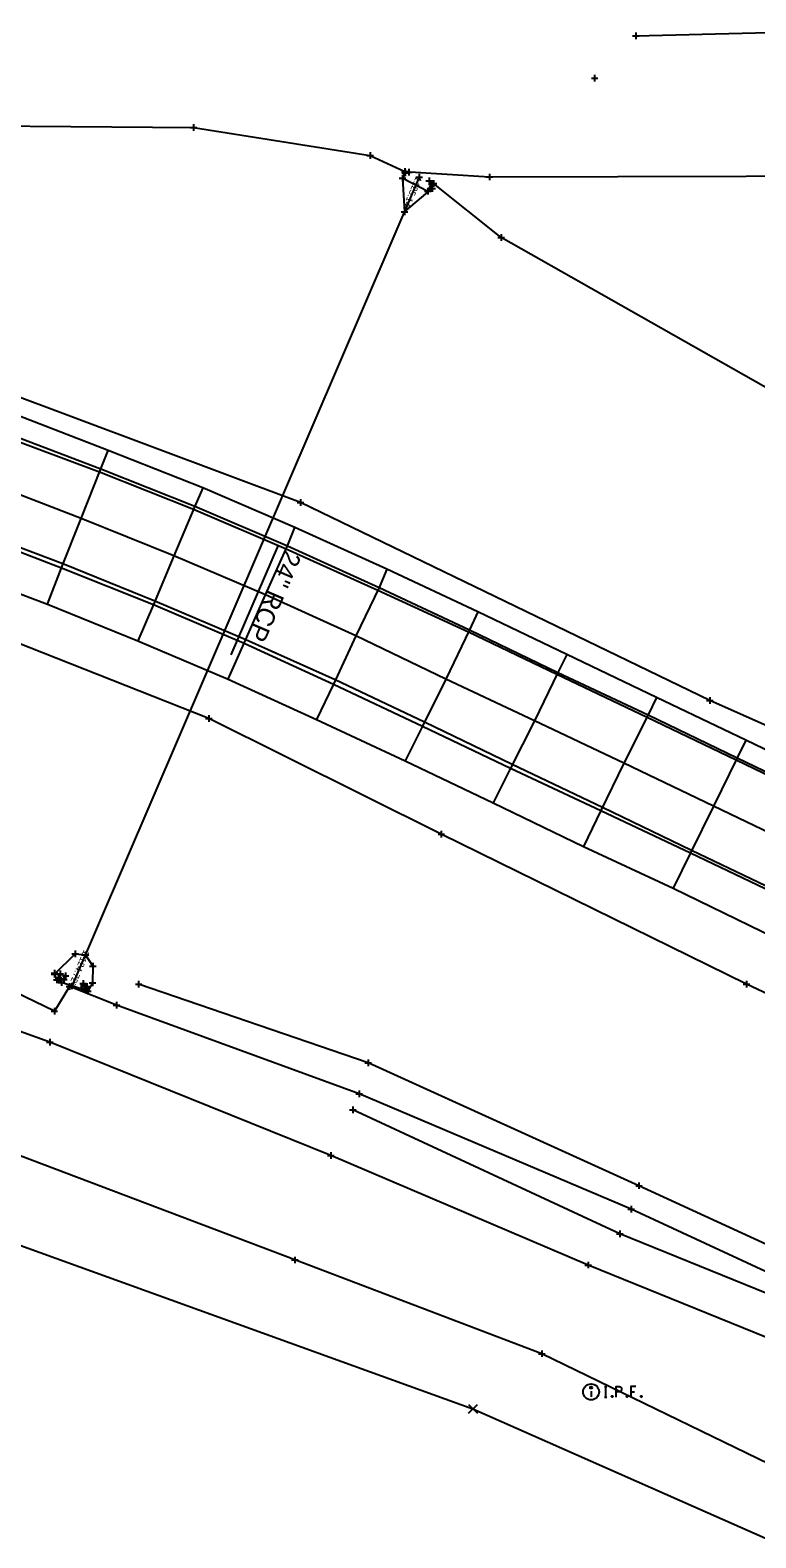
# Model space of a CAD drawing. Extents: x 207090 to 277928, y 600777 to 621109.
# Drawn here: x 259988 to 260097.7, y 611751.4 to 611979.1 of the extents above; entities that cross this region are included whole.
import ezdxf

# ---------------------------------------------------------------- set-up
doc = ezdxf.new("R2010")
doc.units = 0
for name, color, linetype in [('ATDIMS', 7, 'Continuous'), ('DR_X_Ditch', 7, 'Continuous'), ('DR_X_Headwall', 7, 'Continuous'), ('DR_X_Storm_Sewer', 7, 'Continuous'), ('DR_X_Text', 7, 'Continuous'), ('DT_X_Break_Line', 7, 'Continuous'), ('PM_P_Channelizing_Line', 7, 'Continuous'), ('PM_P_Edge_Line', 7, 'Continuous'), ('PM_P_Lane_Line', 7, 'Continuous'), ('PM_P_Stop_Line', 7, 'Continuous'), ('PM_X_Edge_Line', 7, 'Continuous'), ('PV_X_EOP', 7, 'Continuous'), ('PV_X_Joint', 7, 'Continuous'), ('PV_X_Shoulder_Aggregate', 7, 'Continuous'), ('SC_ProfileRun2', 7, 'Continuous'), ('SV_X_Break_Lines', 7, 'Continuous'), ('SV_X_Terrain_Boundary', 7, 'Continuous'), ('SV_X_Toe_of_Slope', 7, 'Continuous')]:
    doc.layers.add(name, color=color, linetype=linetype)

msp = doc.modelspace()

# ---------------------------------------------------------------- linework, layer by layer
at = {"layer": 'DR_X_Ditch'}
for points in [[(259994.32, 611834.74), (259993.95, 611834.65), (259991.68, 611830.94), (259953.06, 611849.58), (259908.97, 611863.06), (259861.24, 611870.04), (259813, 611875.04), (259773.78, 611878.41), (259728.19, 611880.81), (259679.51, 611881.44), (259609.96, 611884.9), (259573.89, 611884.86), (259525.74, 611886.2)], [(260922.71, 611564.11), (260890.1, 611570.61), (260838.53, 611574.76), (260802.48, 611577.5), (260766.37, 611577.17), (260721.33, 611574.97), (260650.56, 611573.72), (260623.07, 611583.7), (260580.3, 611596.7), (260534.96, 611609.27), (260480.65, 611625.85), (260438.14, 611643.07), (260395.35, 611661.63), (260359.84, 611676.62), (260316.28, 611695.06), (260281.01, 611710.64), (260238.37, 611728.41), (260199.78, 611745.66), (260157.66, 611763.38), (260118.67, 611782.58), (260078.85, 611801.04), (260037.76, 611818.47), (260001.09, 611831.86), (259993.95, 611834.65)]]:
    msp.add_lwpolyline(points, dxfattribs=at)
at = {"layer": 'DR_X_Headwall'}
for p, q in [((259992.33, 611835.96), (259992.58, 611836.57)), ((259995.73, 611834.41), (259996.02, 611835.14))]:
    msp.add_line(p, q, dxfattribs=at)
for points in [[(260044.7, 611957.54), (260044.32, 611956.73), (260048.11, 611954.79), (260048.7, 611955.83)], [(259992.58, 611836.57), (259993.39, 611836.26), (259993.11, 611835.72), (259992.33, 611835.96)], [(259995.73, 611834.41), (259996.36, 611834.16), (259996.61, 611834.68), (259996.02, 611835.14)]]:
    msp.add_lwpolyline(points, dxfattribs=at)
at = {"layer": 'DR_X_Storm_Sewer'}
msp.add_line((260046.81, 611956.88), (259994.32, 611834.74), dxfattribs=at)
at = {"layer": 'DR_X_Text'}
msp.add_line((260018.42, 611884.73), (260025.55, 611901.32), dxfattribs=at)
at = {"layer": 'DT_X_Break_Line'}
msp.add_lwpolyline([(259527, 611849.97), (259626.95, 611842.34), (259741, 611827.05), (259865.07, 611829.81), (259960.08, 611805.1), (260054.94, 611770.89), (260146.45, 611730.46), (260219.24, 611692.26), (260311.2, 611653.27), (260395, 611624.63), (260483.4, 611590.72), (260567.09, 611557.23), (260605.33, 611542.61), (260696.47, 611540.48), (260809.17, 611536.63), (260899.87, 611536.02), (260901.21, 611486.51)], dxfattribs=at)
at = {"layer": 'PM_P_Channelizing_Line'}
msp.add_line((260072.79, 611773.57), (260072.79, 611772.68), dxfattribs=at)
for points in [[(260074.82, 611774.25), (260075.17, 611774.25)], [(260075, 611772.65), (260075, 611774.25)], [(260076.56, 611772.65), (260076.56, 611774.25), (260077.09, 611774.25), (260077.15, 611774.24), (260077.22, 611774.21), (260077.26, 611774.19), (260077.29, 611774.16), (260077.33, 611774.1), (260077.37, 611774.04), (260077.39, 611773.94), (260077.39, 611773.78), (260077.38, 611773.73), (260077.36, 611773.66), (260077.31, 611773.57), (260077.27, 611773.53), (260077.24, 611773.51), (260077.18, 611773.48), (260077.09, 611773.47), (260076.56, 611773.47)], [(260079.57, 611774.25), (260078.81, 611774.25), (260078.81, 611772.65)], [(260078.81, 611773.47), (260079.35, 611773.47)], [(260074.82, 611772.65), (260075.17, 611772.65)], [(260075.96, 611772.86), (260076.01, 611772.86), (260076.04, 611772.84), (260076.08, 611772.79), (260076.08, 611772.73), (260076.04, 611772.68), (260076.01, 611772.65), (260075.96, 611772.65), (260075.92, 611772.68), (260075.89, 611772.73), (260075.89, 611772.79), (260075.92, 611772.84), (260075.96, 611772.86)], [(260078.21, 611772.86), (260078.26, 611772.86), (260078.29, 611772.84), (260078.33, 611772.79), (260078.33, 611772.73), (260078.29, 611772.68), (260078.26, 611772.65), (260078.21, 611772.65), (260078.17, 611772.68), (260078.14, 611772.73), (260078.14, 611772.79), (260078.17, 611772.84), (260078.21, 611772.86)], [(260080.35, 611772.86), (260080.41, 611772.86), (260080.44, 611772.84), (260080.48, 611772.79), (260080.48, 611772.73), (260080.44, 611772.68), (260080.41, 611772.65), (260080.35, 611772.65), (260080.32, 611772.68), (260080.29, 611772.73), (260080.29, 611772.79), (260080.32, 611772.84), (260080.35, 611772.86)]]:
    msp.add_lwpolyline(points, dxfattribs=at)
for centre, radius in [((260072.79, 611773.45), 1.2), ((260072.79, 611774.1), 0.16)]:
    msp.add_circle(centre, radius, dxfattribs=at)
at = {"layer": 'PM_P_Edge_Line'}
for points in [[(260941.7, 611641.82), (260872.52, 611643.41), (260802.13, 611645.93), (260739.12, 611642.18), (260643.19, 611651.33), (260585.03, 611658.8), (260513.53, 611682.15), (260464, 611705.03), (260398.1, 611738.54), (260342.54, 611761.22), (260280.51, 611790.45), (260220.82, 611821.35), (260149.95, 611851.52), (260090.72, 611877.86), (260028.89, 611907.76), (259972.46, 611928.83), (259918.28, 611945.99), (259861.48, 611959.13), (259802.38, 611969.56)], [(260619.36, 611566.48), (260576.53, 611581.12), (260531.14, 611596.48), (260474.62, 611616.67), (260434.35, 611631.77), (260391.22, 611651.53), (260353.46, 611665.22), (260309.89, 611681.18), (260273.05, 611696.19), (260231.58, 611714.55), (260192.39, 611733.11), (260152.26, 611751.99), (260115.57, 611775.09), (260072.37, 611792.61), (260033.48, 611809.15), (259991.01, 611826.28), (259950.11, 611840.93)]]:
    msp.add_lwpolyline(points, dxfattribs=at)
at = {"layer": 'PM_P_Lane_Line'}
msp.add_lwpolyline([(260617.29, 611547.1), (260564.97, 611566.43), (260527.38, 611581.13), (260467.61, 611603.71), (260430.24, 611617.6), (260385.39, 611634.96), (260347.72, 611648.56), (260302.9, 611665.18), (260265.68, 611679.36), (260222.59, 611700.28), (260186.67, 611718.31), (260144.42, 611739.84), (260108.32, 611758.38), (260065.34, 611779.22), (260028.03, 611793.37), (259983.16, 611810.37)], dxfattribs=at)
at = {"layer": 'PM_P_Stop_Line'}
for p, q in [((260079.54, 611978.73), (260079.54, 611977.73)), ((260079.04, 611978.23), (260080.04, 611978.23)), ((260079.54, 611978.23), (260079.54, 611978.23)), ((260012.72, 611964.89), (260012.72, 611963.89)), ((260012.22, 611964.39), (260013.22, 611964.39)), ((260012.72, 611964.39), (260012.72, 611964.39)), ((260038.89, 611960.15), (260039.89, 611960.15)), ((260039.39, 611960.65), (260039.39, 611959.65)), ((260039.39, 611960.15), (260039.39, 611960.15)), ((260044.66, 611958.26), (260044.66, 611957.26)), ((260044.7, 611958.04), (260044.7, 611957.04)), ((260045.25, 611958.15), (260045.25, 611957.15)), ((260043.77, 611956.74), (260044.77, 611956.74)), ((260043.82, 611956.73), (260044.82, 611956.73)), ((260044.16, 611957.76), (260045.16, 611957.76)), ((260044.2, 611957.54), (260045.2, 611957.54)), ((260044.27, 611957.24), (260044.27, 611956.24)), ((260044.27, 611956.74), (260044.27, 611956.74)), ((260044.32, 611957.23), (260044.32, 611956.23)), ((260044.32, 611956.73), (260044.32, 611956.73)), ((260044.66, 611957.76), (260044.66, 611957.76)), ((260044.7, 611957.54), (260044.7, 611957.54)), ((260044.75, 611957.65), (260045.75, 611957.65)), ((260045.25, 611957.65), (260045.25, 611957.65)), ((260047.82, 611956.35), (260048.82, 611956.35)), ((260048.2, 611955.83), (260049.2, 611955.83)), ((260048.32, 611956.85), (260048.32, 611955.85)), ((260048.32, 611956.35), (260048.32, 611956.35)), ((260048.47, 611955.93), (260049.47, 611955.93)), ((260048.7, 611956.33), (260048.7, 611955.33)), ((260048.7, 611955.83), (260048.7, 611955.83)), ((260048.76, 611955.65), (260048.76, 611954.65)), ((260048.97, 611956.43), (260048.97, 611955.43)), ((260048.97, 611955.93), (260048.97, 611955.93)), ((260056.93, 611956.91), (260057.93, 611956.91)), ((260057.43, 611957.41), (260057.43, 611956.41)), ((260057.43, 611956.91), (260057.43, 611956.91)), ((260047.61, 611954.79), (260048.61, 611954.79)), ((260048.11, 611955.29), (260048.11, 611954.29)), ((260048.11, 611954.79), (260048.11, 611954.79)), ((260048.26, 611955.15), (260049.26, 611955.15)), ((260048.76, 611955.15), (260048.76, 611955.15)), ((260044.09, 611951.63), (260045.09, 611951.63)), ((260044.59, 611952.13), (260044.59, 611951.13)), ((260044.59, 611951.63), (260044.59, 611951.63)), ((260058.71, 611947.76), (260059.71, 611947.76)), ((260059.21, 611948.26), (260059.21, 611947.26)), ((260059.21, 611947.76), (260059.21, 611947.76)), ((260028.39, 611907.76), (260029.39, 611907.76)), ((260028.89, 611908.26), (260028.89, 611907.26)), ((260028.89, 611907.76), (260028.89, 611907.76)), ((260090.72, 611878.36), (260090.72, 611877.36)), ((260090.22, 611877.86), (260091.22, 611877.86)), ((260090.72, 611877.86), (260090.72, 611877.86)), ((260014.54, 611875.15), (260015.54, 611875.15)), ((260015.04, 611875.65), (260015.04, 611874.65)), ((260015.04, 611875.15), (260015.04, 611875.15)), ((260049.66, 611857.67), (260050.66, 611857.67)), ((260050.16, 611858.17), (260050.16, 611857.17)), ((260050.16, 611857.67), (260050.16, 611857.67)), ((259994.33, 611839.58), (259995.33, 611839.58)), ((259994.83, 611840.08), (259994.83, 611839.08)), ((259994.83, 611839.58), (259994.83, 611839.58)), ((259995.91, 611839.43), (259996.91, 611839.43)), ((259996.41, 611839.93), (259996.41, 611838.93)), ((259996.41, 611839.43), (259996.41, 611839.43)), ((259991.69, 611837.2), (259991.69, 611836.2)), ((259997.01, 611837.75), (259998.01, 611837.75)), ((259997.51, 611838.25), (259997.51, 611837.25)), ((259997.51, 611837.75), (259997.51, 611837.75)), ((259991.18, 611836.53), (259992.18, 611836.53)), ((259991.19, 611836.7), (259992.19, 611836.7)), ((259991.54, 611835.65), (259992.54, 611835.65)), ((259991.68, 611837.03), (259991.68, 611836.03)), ((259991.68, 611836.53), (259991.68, 611836.53)), ((259991.69, 611836.7), (259991.69, 611836.7)), ((259991.83, 611835.96), (259992.83, 611835.96)), ((259992.04, 611836.15), (259992.04, 611835.15)), ((259992.04, 611835.65), (259992.04, 611835.65)), ((259992.08, 611836.57), (259993.08, 611836.57)), ((259992.27, 611835.25), (259993.27, 611835.25)), ((259992.33, 611836.46), (259992.33, 611835.46)), ((259992.33, 611835.96), (259992.33, 611835.96)), ((259992.58, 611837.07), (259992.58, 611836.07)), ((259992.58, 611836.57), (259992.58, 611836.57)), ((259992.61, 611835.72), (259993.61, 611835.72)), ((259992.77, 611835.75), (259992.77, 611834.75)), ((259992.77, 611835.25), (259992.77, 611835.25)), ((259992.89, 611836.26), (259993.89, 611836.26)), ((259993.11, 611836.22), (259993.11, 611835.22)), ((259993.11, 611835.72), (259993.11, 611835.72)), ((259993.39, 611836.76), (259993.39, 611835.76)), ((259993.39, 611836.26), (259993.39, 611836.26)), ((259993.95, 611835.15), (259993.95, 611834.15)), ((259995.52, 611835.14), (259996.52, 611835.14)), ((259995.73, 611834.91), (259995.73, 611833.91)), ((259996.02, 611835.64), (259996.02, 611834.64)), ((259996.02, 611835.14), (259996.02, 611835.14)), ((259996.61, 611835.18), (259996.61, 611834.18)), ((259996.96, 611835.24), (259997.96, 611835.24)), ((259997.46, 611835.74), (259997.46, 611834.74)), ((259997.46, 611835.24), (259997.46, 611835.24)), ((260003.92, 611835), (260004.92, 611835)), ((260004.42, 611835.5), (260004.42, 611834.5)), ((260004.42, 611835), (260004.42, 611835)), ((260095.76, 611835.04), (260096.76, 611835.04)), ((260096.26, 611835.54), (260096.26, 611834.54)), ((260096.26, 611835.04), (260096.26, 611835.04)), ((259993.45, 611834.65), (259994.45, 611834.65)), ((259993.95, 611834.65), (259993.95, 611834.65)), ((259995.23, 611834.41), (259996.23, 611834.41)), ((259995.73, 611834.41), (259995.73, 611834.41)), ((259995.86, 611834.16), (259996.86, 611834.16)), ((259996.11, 611834.68), (259997.11, 611834.68)), ((259996.22, 611833.96), (259997.22, 611833.96)), ((259996.36, 611834.66), (259996.36, 611833.66)), ((259996.36, 611834.16), (259996.36, 611834.16)), ((259996.61, 611834.68), (259996.61, 611834.68)), ((259996.72, 611834.46), (259996.72, 611833.46)), ((259996.72, 611833.96), (259996.72, 611833.96)), ((259991.18, 611830.94), (259992.18, 611830.94)), ((259991.68, 611831.44), (259991.68, 611830.44)), ((259991.68, 611830.94), (259991.68, 611830.94)), ((260000.59, 611831.86), (260001.59, 611831.86)), ((260001.09, 611832.36), (260001.09, 611831.36)), ((260001.09, 611831.86), (260001.09, 611831.86)), ((259990.51, 611826.28), (259991.51, 611826.28)), ((259991.01, 611826.78), (259991.01, 611825.78)), ((259991.01, 611826.28), (259991.01, 611826.28)), ((260039.11, 611823.62), (260039.11, 611822.62)), ((260038.61, 611823.12), (260039.61, 611823.12)), ((260039.11, 611823.12), (260039.11, 611823.12)), ((260037.76, 611818.97), (260037.76, 611817.97)), ((260037.26, 611818.47), (260038.26, 611818.47)), ((260037.76, 611818.47), (260037.76, 611818.47)), ((260036.28, 611816.05), (260037.28, 611816.05)), ((260036.78, 611816.55), (260036.78, 611815.55)), ((260036.78, 611816.05), (260036.78, 611816.05)), ((260032.98, 611809.15), (260033.98, 611809.15)), ((260033.48, 611809.65), (260033.48, 611808.65)), ((260033.48, 611809.15), (260033.48, 611809.15)), ((260079.53, 611804.59), (260080.53, 611804.59)), ((260080.03, 611805.09), (260080.03, 611804.09)), ((260080.03, 611804.59), (260080.03, 611804.59)), ((260078.35, 611801.04), (260079.35, 611801.04)), ((260078.85, 611801.54), (260078.85, 611800.54)), ((260078.85, 611801.04), (260078.85, 611801.04)), ((260076.65, 611797.3), (260077.65, 611797.3)), ((260077.15, 611797.8), (260077.15, 611796.8)), ((260077.15, 611797.3), (260077.15, 611797.3)), ((260027.53, 611793.37), (260028.53, 611793.37)), ((260028.03, 611793.87), (260028.03, 611792.87)), ((260028.03, 611793.37), (260028.03, 611793.37)), ((260071.87, 611792.61), (260072.87, 611792.61)), ((260072.37, 611793.11), (260072.37, 611792.11)), ((260072.37, 611792.61), (260072.37, 611792.61)), ((260064.84, 611779.22), (260065.84, 611779.22)), ((260065.34, 611779.72), (260065.34, 611778.72)), ((260065.34, 611779.22), (260065.34, 611779.22))]:
    msp.add_line(p, q, dxfattribs=at)
at = {"layer": 'PM_X_Edge_Line'}
for p, q in [((260054.27, 611770.22), (260055.61, 611771.56)), ((260054.27, 611771.56), (260055.61, 611770.22))]:
    msp.add_line(p, q, dxfattribs=at)
for points in [[(259984.34, 611917.67), (259998.52, 611912.37), (260012.72, 611906.76), (260026.7, 611900.75), (260040.56, 611894.52), (260054.26, 611888.21), (260067.64, 611881.84), (260081.26, 611875.35), (260094.72, 611868.88), (260108.32, 611862.35), (260121.93, 611855.9), (260135.42, 611849.42), (260148.77, 611842.98), (260162.55, 611836.52), (260175.97, 611830.01), (260189.46, 611823.51), (260202.99, 611817.14), (260216.7, 611810.62), (260230.02, 611804.27), (260243.69, 611797.74), (260257.03, 611791.28), (260270.66, 611784.79), (260284.2, 611778.26), (260297.71, 611771.7)], [(260291.07, 611758.25), (260277.66, 611764.84), (260264.07, 611771.24), (260250.44, 611777.65), (260237, 611784.15), (260223.45, 611790.71), (260209.88, 611797.09), (260196.37, 611803.55), (260182.8, 611809.97), (260169.28, 611816.44), (260155.76, 611822.92), (260142.12, 611829.38), (260128.56, 611835.74), (260115.05, 611842.19), (260101.47, 611848.77), (260087.95, 611855.18), (260074.51, 611861.71), (260060.89, 611868.2), (260047.6, 611874.59), (260034.14, 611880.98), (260020.62, 611887.03), (260006.87, 611892.87), (259992.98, 611898.5), (259979.07, 611903.75)]]:
    msp.add_lwpolyline(points, dxfattribs=at)
at = {"layer": 'PV_X_EOP'}
for points in [[(260299.25, 611775.02), (260285.78, 611781.51), (260272.19, 611787.95), (260258.56, 611794.44), (260245.22, 611800.68), (260231.52, 611807.25), (260218.3, 611813.59), (260204.53, 611820.23), (260191.03, 611826.59), (260177.46, 611833.09), (260163.99, 611839.58), (260150.29, 611845.97), (260136.95, 611852.46), (260123.4, 611858.95), (260109.7, 611865.39), (260096.16, 611871.85), (260082.69, 611878.29), (260069.14, 611884.78), (260055.69, 611891.22), (260041.95, 611897.69), (260028, 611903.96), (260014.1, 611909.97), (259999.81, 611915.61), (259985.53, 611921.15)], [(259976.73, 611897.65), (259990.63, 611892.38), (260004.3, 611886.85), (260017.97, 611881.08), (260031.32, 611874.99), (260044.72, 611868.73), (260057.99, 611862.41), (260071.66, 611855.82), (260085.21, 611849.51), (260098.63, 611842.99), (260112.25, 611836.45), (260125.72, 611830.01), (260139.27, 611823.47), (260152.84, 611816.95), (260166.41, 611810.46), (260179.98, 611804.07), (260193.55, 611797.63), (260206.97, 611791.12), (260220.44, 611784.63), (260234.04, 611778.14), (260247.56, 611771.72), (260261.28, 611765.31), (260274.68, 611758.82), (260288.12, 611752.32)]]:
    msp.add_lwpolyline(points, dxfattribs=at)
at = {"layer": 'PV_X_Joint'}
for points in [[(259984.56, 611918.24), (259998.71, 611912.85), (260012.9, 611907.19), (260026.9, 611901.2), (260040.75, 611894.91), (260054.42, 611888.54), (260067.76, 611882.1), (260081.44, 611875.71), (260094.88, 611869.2), (260108.48, 611862.66), (260122.05, 611856.14), (260135.55, 611849.68), (260148.92, 611843.28), (260162.64, 611836.69), (260176.13, 611830.35), (260189.68, 611823.96), (260203.15, 611817.47), (260216.85, 611810.91), (260230.14, 611804.52), (260243.82, 611798), (260257.19, 611791.61), (260270.83, 611785.15), (260284.35, 611778.58), (260297.93, 611772.14)], [(259990.63, 611892.38), (259992.74, 611897.91), (259995.75, 611905.33), (259998.71, 611912.85), (259999.81, 611915.61)], [(260294.36, 611764.92), (260280.84, 611771.37), (260267.3, 611777.86), (260253.72, 611784.36), (260240.24, 611790.81), (260226.59, 611797.31), (260213.25, 611803.72), (260199.6, 611810.25), (260186.12, 611816.68), (260172.6, 611823.11), (260159.03, 611829.56), (260145.44, 611836.09), (260131.97, 611842.46), (260118.45, 611848.91), (260104.84, 611855.42), (260091.29, 611861.89), (260077.74, 611868.37), (260064.22, 611874.78), (260050.84, 611881.1), (260037.25, 611887.61), (260023.61, 611893.83), (260009.76, 611899.71), (259995.75, 611905.33), (259981.72, 611910.72)], [(260014.1, 611909.97), (260012.9, 611907.19), (260009.76, 611899.71), (260006.66, 611892.36), (260004.3, 611886.85)], [(259978.87, 611903.22), (259992.74, 611897.91), (260006.66, 611892.36), (260020.38, 611886.49), (260033.84, 611880.34), (260047.31, 611873.99), (260060.6, 611867.62), (260074.26, 611861.22), (260087.79, 611854.85), (260101.29, 611848.43), (260114.89, 611841.87), (260128.44, 611835.5), (260141.96, 611829.06), (260155.48, 611822.35), (260169.04, 611815.95), (260182.54, 611809.45), (260196.11, 611803.01), (260209.6, 611796.55), (260223.15, 611790.08), (260236.73, 611783.6), (260250.18, 611777.1), (260263.76, 611770.59), (260277.31, 611764.13), (260290.8, 611757.7)], [(260017.97, 611881.08), (260020.38, 611886.49), (260023.61, 611893.83), (260026.9, 611901.2), (260028, 611903.96)], [(260041.95, 611897.69), (260040.75, 611894.91), (260037.25, 611887.61), (260033.84, 611880.34), (260031.32, 611874.99)], [(260055.69, 611891.22), (260054.42, 611888.54), (260050.84, 611881.1), (260047.31, 611873.99), (260044.72, 611868.73)], [(260069.14, 611884.78), (260067.76, 611882.1), (260064.22, 611874.78), (260060.6, 611867.62), (260057.99, 611862.41)], [(260082.69, 611878.29), (260081.44, 611875.71), (260077.74, 611868.37), (260074.26, 611861.22), (260071.66, 611855.82)], [(260096.16, 611871.85), (260094.88, 611869.2), (260091.29, 611861.89), (260087.79, 611854.85), (260085.21, 611849.51)]]:
    msp.add_lwpolyline(points, dxfattribs=at)
at = {"layer": 'PV_X_Shoulder_Aggregate'}
msp.add_lwpolyline([(260588.39, 611617.67), (260541.9, 611632.04), (260489.56, 611649.03), (260447.9, 611661.5), (260406.19, 611684.2), (260370.02, 611699.71), (260327.85, 611720.53), (260291.62, 611734.37), (260249.96, 611756.38), (260214.28, 611773.53), (260175.37, 611794.78), (260134.19, 611817.22), (260096.26, 611835.04), (260050.16, 611857.67), (260015.04, 611875.15), (259964.77, 611894.99)], dxfattribs=at)
at = {"layer": 'SC_ProfileRun2'}
for p, q in [((260072.83, 611971.83), (260073.83, 611971.83)), ((260073.33, 611972.33), (260073.33, 611971.33)), ((260073.33, 611971.83), (260073.33, 611971.83)), ((260046.31, 611956.88), (260047.31, 611956.88)), ((260046.81, 611957.38), (260046.81, 611956.38)), ((260046.81, 611956.88), (260046.81, 611956.88)), ((259994.32, 611835.24), (259994.32, 611834.24)), ((259993.82, 611834.74), (259994.82, 611834.74)), ((259994.32, 611834.74), (259994.32, 611834.74))]:
    msp.add_line(p, q, dxfattribs=at)
at = {"layer": 'SV_X_Break_Lines'}
for points in [[(260079.54, 611978.23), (260147.85, 611979.94), (260224.94, 611984.58), (260283.63, 611986.33), (260376.17, 611993.45), (260430.98, 611997.97), (260501.33, 612005.92), (260568.19, 612012.52), (260665.39, 612021.82), (260738.5, 612025.23), (260878.18, 612033.24), (260945.62, 612043.68), (260962.47, 612054.69)], [(260045.25, 611957.65), (260044.66, 611957.76), (260044.27, 611956.74), (260044.59, 611951.63), (260048.76, 611955.15), (260048.97, 611955.93), (260048.32, 611956.35)]]:
    msp.add_lwpolyline(points, dxfattribs=at)
msp.add_lwpolyline([(259992.77, 611835.25), (259992.04, 611835.65), (259991.68, 611836.53), (259994.83, 611839.58), (259996.41, 611839.43), (259997.51, 611837.75), (259997.46, 611835.24), (259996.72, 611833.96)], close=True, dxfattribs=at)
at = {"layer": 'SV_X_Terrain_Boundary'}
msp.add_lwpolyline([(259960.08, 611805.1), (260054.94, 611770.89), (260146.45, 611730.46), (260219.24, 611692.26), (260311.2, 611653.27), (260395, 611624.63), (260483.4, 611590.72), (260567.09, 611557.23), (260605.33, 611542.61), (260696.47, 611540.48), (260809.17, 611536.63), (260899.87, 611536.02), (260901.21, 611486.51), (260897.37, 611436.68), (260893.26, 611381.88), (260887.57, 611336.25), (260889.23, 611327.21), (260898.32, 611326.76), (260915.52, 611324.45), (260918.27, 611325.53), (260925.91, 611325.5), (260944.43, 611323.83), (260949.14, 611332.66)], dxfattribs=at)
at = {"layer": 'SV_X_Toe_of_Slope'}
for points in [[(260057.43, 611956.91), (260154.39, 611957.2), (260210.6, 611959.18), (260290.65, 611965.54), (260371.8, 611968.5), (260434.33, 611973.43), (260503.32, 611976.43), (260573.59, 611981.28), (260664.56, 611990.82), (260741.56, 611999.54), (260817.01, 612000.56), (260885.81, 612009.06), (260927.83, 612013.08)], [(259796.51, 611977.51), (259855.08, 611973.39), (259910.76, 611969.29), (259963.24, 611964.8), (260012.72, 611964.39), (260039.39, 611960.15), (260044.66, 611957.76), (260057.43, 611956.91)], [(260584.49, 611679.87), (260523.52, 611705.96), (260471.88, 611729.74), (260409.9, 611761.84), (260354.73, 611791.77), (260297.31, 611822.41), (260235.39, 611854.87), (260171.14, 611888.31), (260107.91, 611920.17), (260059.21, 611947.76), (260048.97, 611955.93)], [(260623.87, 611586.69), (260580.98, 611599.92), (260535.83, 611612.68), (260481.36, 611629.91), (260439.56, 611645.65), (260396.5, 611665.29), (260360.67, 611680.75), (260319.29, 611699.51), (260282.24, 611713.76), (260240.47, 611733.47), (260201.44, 611750.83), (260160.36, 611768), (260121.13, 611785.67), (260080.03, 611804.59), (260039.11, 611823.12), (260004.42, 611835)], [(260622.6, 611579.61), (260579.7, 611593.18), (260534.17, 611606.7), (260479.56, 611623.16), (260436.94, 611640.25), (260394.59, 611658.68), (260357.76, 611673.81), (260315.03, 611691.85), (260278.88, 611706.48), (260238.14, 611725.71), (260197.75, 611742.19), (260155.58, 611761.21), (260118.33, 611780.62), (260077.15, 611797.3), (260036.78, 611816.05)]]:
    msp.add_lwpolyline(points, dxfattribs=at)

# ---------------------------------------------------------------- texts
at = {"layer": 'ATDIMS'}
for s, p in [("1125.14'", (260046.35, 611957.08)), ("1,124.72'", (259996.14, 611840.25))]:
    msp.add_text(s, height=1, rotation=246.7435, dxfattribs=at).set_placement(p)
at = {"layer": 'DR_X_Text'}
msp.add_text('24" RCP', height=2.8, rotation=246.7435, dxfattribs=at).set_placement((260026.51, 611900.78))

doc.saveas('drawing.dxf')
